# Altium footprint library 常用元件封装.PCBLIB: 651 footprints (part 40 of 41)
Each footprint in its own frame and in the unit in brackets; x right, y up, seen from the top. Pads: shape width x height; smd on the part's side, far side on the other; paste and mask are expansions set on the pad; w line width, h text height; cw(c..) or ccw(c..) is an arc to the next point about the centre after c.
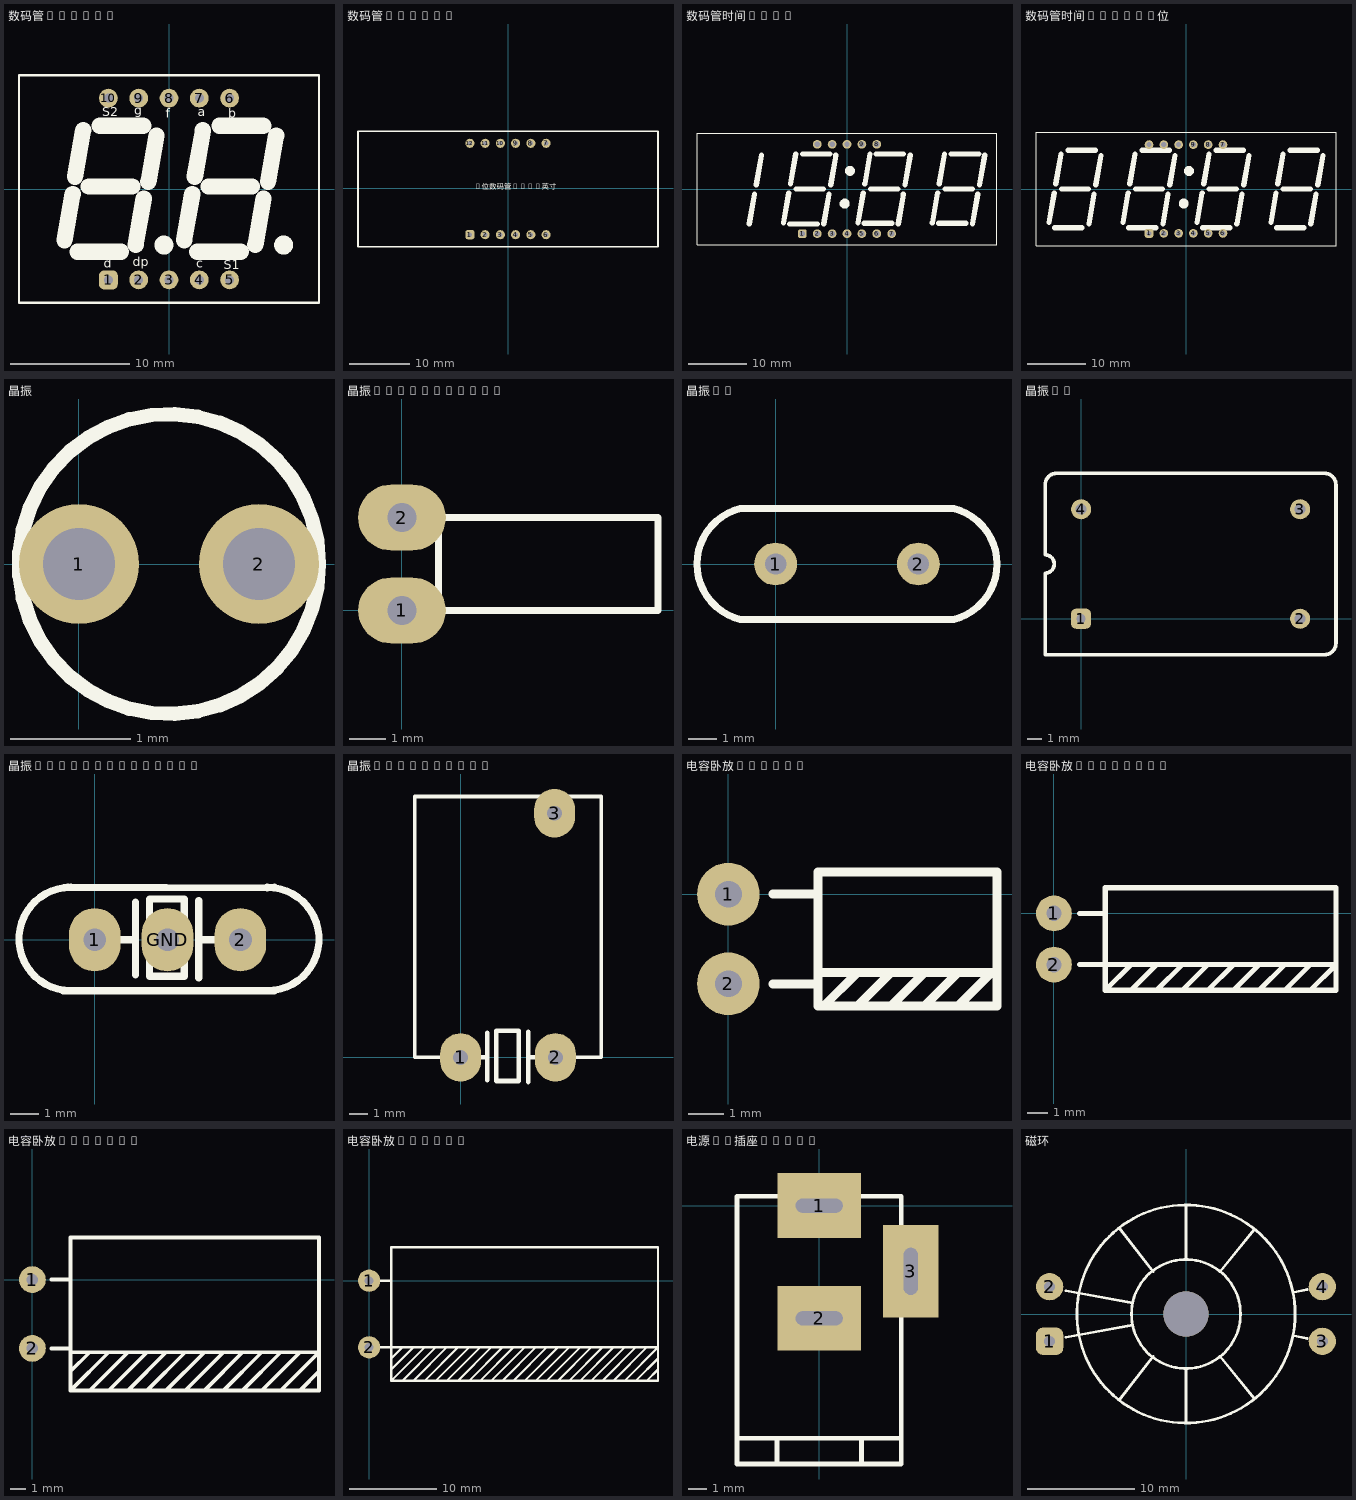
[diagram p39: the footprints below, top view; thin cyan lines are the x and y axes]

## 数码管0.56/2 [mil]
pads (10):
  rrect50% 62x62 hole 30: 1(-200,-300)
  round 62 hole 30: 2(-100,-300) 3(0,-300) 4(100,-300) 5(200,-300) 6(200,300) 7(100,300) 8(0,300) 9(-100,300) 10(-200,300)
TopOverlay:
  circle w39.37: c-16.65,-185 r11.65
  circle w39.37: c378.35,-185 r11.65
  lines w8: -495,-375 -495,375 495,375 495,-375 -495,-375
  lines w53.94: -345.05,-169.44 -318.18,-16.55 ; -310,40.42 -283.18,193.45 ; -301.9,-206.67 -158.18,-206.55 ; -264.89,8.45 -121.23,8.45 ; -228.18,208.45 -84.52,208.45 ; -110.17,-184.51 -83.18,-31.55 ; -68.18,23.45 -41.27,176.54 ; 49.95,-169.44 76.82,-16.55 ; 85,40.42 111.82,193.45 ; 93.1,-206.67 236.82,-206.55 ; 130.11,8.45 273.77,8.45 ; 166.82,208.45 310.48,208.45 ; 284.83,-184.51 311.82,-31.55 ; 326.82,23.45 353.73,176.54
  text "S1" at 180,-265 h30
  text "S2" at -220,240 h30
  text "g" at -115,245 h30
  text "f" at -10,235 h30
  text "a" at 95,240 h30
  text "b" at 195,235 h30
  text "d" at -215,-260 h30
  text "e" at -20,-200 h30
  text "c" at 90,-260 h30
  text "dp" at -120,-255 h30
  text "e" at 375,-200 h30

## 数码管0.56/4 [mil] "50.3mmX19mm"
pads (12):
  rrect50% 60x60 hole 30: 1(-250,-305)
  round 60 hole 30: 2(-150,-305) 3(-50,-305) 4(50,-305) 5(150,-305) 6(250,-305) 7(250,295) 8(150,295) 9(50,295) 10(-50,295) 11(-150,295) 12(-250,295)
TopOverlay:
  lines w10: -985,-385 970,-385 985,-385 985,375 -985,375 -985,-385
  text "4位数码管0.56英寸" at -220,-20 h60

## 数码管时间0.56 [mm] "LED, 7-Segment Display, 14.22 mm, Four Digit, 18:88; 12 Leads; Row Space 15.24 mm; Pitch 2.54 mm"
height 8.26
pads (12):
  rrect50% 1.5x1.5 hole 0.9: 1(-7.62,-7.62)
  round 1.5 hole 0.9: 2(-5.08,-7.62) 3(-2.54,-7.62) 4(0,-7.62) 5(2.54,-7.62) 6(5.08,-7.62) 7(7.62,-7.62) 8(5.08,7.62) 9(2.54,7.62) 10(0,7.62) 11(-2.54,7.62) 12(-5.08,7.62)
TopOverlay:
  circle w1.4: c0.505,3.1 r0.15
  circle w1.4: c-0.395,-2.5 r0.15
  lines w0.2: -25.6,-9.55 25.6,-9.55 25.6,9.55 -25.6,9.55 -25.6,-9.55
  lines w0.9: -16.67,-5.95 -15.78,-0.9 ; -15.49,0.71 -14.6,5.76 ; -10.83,-5.76 -9.93,-0.69 ; -9.75,-5.959 -5.08,-5.969 ; -9.65,0.9 -8.76,5.96 ; -8.69,0 -4.03,0 ; -7.591,5.969 -2.921,5.969 ; -3.97,-5.95 -3.08,-0.9 ; -2.79,0.71 -1.9,5.76 ; 1.87,-5.76 2.77,-0.69 ; 2.95,-5.832 7.62,-5.842 ; 3.05,0.9 3.94,5.96 ; 4.01,0 8.67,0 ; 4.982,5.969 9.652,5.969 ; 8.73,-5.95 9.62,-0.9 ; 9.91,0.71 10.8,5.76 ; 14.57,-5.76 15.47,-0.69 ; 15.65,-5.832 20.32,-5.842 ; 15.75,0.9 16.64,5.96 ; 16.71,0 21.37,0 ; 17.809,5.969 22.479,5.969 ; 21.43,-5.95 22.32,-0.9 ; 22.61,0.71 23.5,5.76

## 数码管时间0.56/4位 [mm] "LED, 7-Segment Display, 14.22 mm, Four Digit, 88:88; 12 Leads; Row Space 15.24 mm; Pitch 2.54 mm"
height 8.26
pads (12):
  rrect50% 1.5x1.5 hole 0.9: 1(-6.35,-7.62)
  round 1.5 hole 0.9: 2(-3.81,-7.62) 3(-1.27,-7.62) 4(1.27,-7.62) 5(3.81,-7.62) 6(6.35,-7.62) 7(6.35,7.62) 8(3.81,7.62) 9(1.27,7.62) 10(-1.27,7.62) 11(-3.81,7.62) 12(-6.35,7.62)
TopOverlay:
  circle w1.4: c-0.395,-2.5 r0.15
  circle w1.4: c0.505,3.1 r0.15
  lines w0.2: -25.75,-9.7 25.75,-9.7 25.75,9.7 -25.75,9.7 -25.75,-9.7
  lines w0.9: -23.53,-5.76 -22.63,-0.69 ; -22.57,-6.66 -17.9,-6.67 ; -22.35,0.9 -21.46,5.96 ; -21.39,0 -16.73,0 ; -20.23,6.66 -15.56,6.66 ; -16.67,-5.95 -15.78,-0.9 ; -15.49,0.71 -14.6,5.76 ; -10.83,-5.76 -9.93,-0.69 ; -9.87,-6.66 -5.2,-6.67 ; -9.65,0.9 -8.76,5.96 ; -8.69,0 -4.03,0 ; -7.53,6.66 -2.86,6.66 ; -3.97,-5.95 -3.08,-0.9 ; -2.79,0.71 -1.9,5.76 ; 1.87,-5.76 2.77,-0.69 ; 2.83,-6.66 7.5,-6.67 ; 3.05,0.9 3.94,5.96 ; 4.01,0 8.67,0 ; 5.17,6.66 9.84,6.66 ; 8.73,-5.95 9.62,-0.9 ; 9.91,0.71 10.8,5.76 ; 14.57,-5.76 15.47,-0.69 ; 15.53,-6.66 20.2,-6.67 ; 15.75,0.9 16.64,5.96 ; 16.71,0 21.37,0 ; 17.87,6.66 22.54,6.66 ; 21.43,-5.95 22.32,-0.9 ; 22.61,0.71 23.5,5.76

## 晶振 [mm] "1.5mm"
pads (2):
  round 1 hole 0.6: 1(0,0) 2(1.5,0)
TopOverlay:
  circle w0.12: c0.75,0 r1.25

## 晶振2.5/2/6/2.5 [mm]
pads (2):
  oval 2.4x1.8 hole 0.8: 1(0,0) 2(0,2.54)
TopOverlay:
  lines w0.2: 0,0 7,0 7,2.54 0,2.54 ; 1,0 1,2.54
BottomOverlay:
  lines w0.2: 1.524,0 2.54,0 2.54,0.508 ; 1.524,0.508 2.54,0.508 ; 1.524,2.032 2.54,2.032 ; 1.524,2.54 2.54,2.54 2.54,2.032 ; 3.556,0.508 2.54,0.508 ; 3.556,2.032 2.54,2.032 ; 1.524,1.016 3.556,1.016 3.556,1.524 1.524,1.524 1.524,1.016

## 晶振-1 [mil] "5.08MM"
pads (2):
  round 60 hole 30: 1(0,0) 2(200,0)
TopOverlay:
  lines w10: -49.4,-77.61 cw(c-30,0) -49.4,77.61 249.4,77.61 cw(c230,0) 249.4,-77.61 -49.4,-77.61

## 晶振-3 [mil] "15.24mmX7.62mm"
pads (4):
  rrect50% 55x55 hole 25: 1(0,0)
  round 55 hole 30: 2(600,0) 3(600,300) 4(0,300)
TopOverlay:
  lines w10: -98.5,-98.5 667,-98.5 ccw(c667,-67) 698.5,-67 698.5,367 ccw(c667,367) 667,398.5 -66.5,398.5 ; -98.5,-98.44 -98.5,124 ; -98.5,125 ccw(c-98.5,150) -98.5,175 -98.5,367 cw(c-67,367) -67,398.5

## 晶振/2.5/3/10/5/E2 [mm]
pads (3):
  oval 1.8x2.2 hole 0.8: 1(0,0) 2(5.08,0) GND(2.54,0)
TopOverlay:
  lines w0.254: -1.1,-1.775 6.266,-1.775 ; -0.94,1.829 6.02,1.803 6.274,1.829 ; -0.838,-1.778 cw(c-0.838,0.025) -0.838,1.829 ; 0,0 1.35,0 ; 1.424,-1.225 1.424,1.315 ; 3.624,-1.325 3.624,1.367 ; 3.65,0 5.08,0 ; 6.02,-1.778 ccw(c6.02,0.025) 6.02,1.829 ; 1.911,-1.27 3.119,-1.27 3.119,1.422 1.911,1.422 1.911,-1.27
BottomOverlay:
  lines w0.254: 0.92,0 1.07,0 ; 1.144,-1.225 1.144,1.315 ; 3.944,-1.325 3.944,1.367 ; 3.99,0 4.12,0 ; 1.631,-1.27 1.631,1.422 3.439,1.422 3.439,-1.27 1.631,-1.27

## 晶振/5/3/14/10 [mm]
pads (3):
  oval 2.2x2.6 hole 0.8: 1(0,0) 2(5.08,0) 3(5.04,13.1)
TopOverlay:
  lines w0.2: 0,0 -2.46,0 -2.46,14 7.54,14 7.54,0 5.08,0
  lines w0.254: 0,0 1.35,0 ; 1.424,-1.225 1.424,1.315 ; 3.624,-1.325 3.624,1.367 ; 3.65,0 5.08,0 ; 1.911,-1.27 1.911,1.422 3.119,1.422 3.119,-1.27 1.911,-1.27
BottomOverlay:
  lines w0.2: -1.66,-1.7 -1.66,1.7 6.74,1.7 6.74,-1.7 -1.66,-1.7
  lines w0.254: 1.45,0 1.6,0 ; 1.744,-1.225 1.744,1.315 ; 3.344,-1.325 3.344,1.367 ; 3.5,0 3.63,0 ; 2.231,-1.27 2.839,-1.27 2.839,1.422 2.231,1.422 2.231,-1.27

## 电容卧放2.54mm [mil] "5.5mmX4mm"
pads (2):
  round 70 hole 30: 1(0,0) 2(0,-100)
TopOverlay:
  lines w10: 50,-100 100,-100 ; 50,0 100,0 ; 100,-87.5 300,-87.5 ; 106.25,-125 143.75,-87.5 ; 143.75,-125 181.25,-87.5 ; 181.25,-125 218.75,-87.5 ; 218.75,-125 256.25,-87.5 ; 256.25,-125 293.75,-87.5 ; 100,-125 100,25 300,25 300,-125 100,-125

## 电容卧放2.54mm-1 [mil] "11.6mmX5.3mm"
pads (2):
  round 70 hole 30: 1(0,0) 2(0,-100)
TopOverlay:
  lines w10: 50,-100 550,-100 500,-150 ; 50,0 100,0 ; 150,-150 200,-100 ; 150,-100 100,-150 ; 200,-150 250,-100 ; 250,-150 300,-100 ; 300,-150 350,-100 ; 350,-150 400,-100 ; 400,-150 450,-100 ; 450,-150 500,-100 ; 100,-150 550,-150 550,50 100,50 100,-150

## 电容卧放4.572mm [mil] "16.8mmX10.5mm"
pads (2):
  round 70 hole 30: 1(0,0) 2(0,-180)
TopOverlay:
  lines w10: 50,-180 100,-180 ; 50,0 100,0 ; 100,-240 150,-190 ; 100,-190 750,-190 650,-290 ; 150,-290 250,-190 ; 200,-290 300,-190 ; 200,-190 100,-290 ; 250,-290 350,-190 ; 300,-290 400,-190 ; 350,-290 450,-190 ; 400,-290 500,-190 ; 450,-290 550,-190 ; 500,-290 600,-190 ; 550,-290 650,-190 ; 600,-290 700,-190 ; 700,-290 750,-240 ; 100,-290 100,110 750,110 750,-290 100,-290

## 电容卧放7.62mm [mm] "30.5mmX15.5mm"
pads (2):
  round 2.54 hole 1: 1(0,0) 2(0,-7.62)
TopOverlay:
  lines w0.254: 1.27,-7.62 33.02,-7.62 29.21,-11.43 ; 1.27,0 2.54,0 ; 2.54,-10.16 5.08,-7.62 ; 2.54,-8.89 3.81,-7.62 ; 3.81,-11.43 7.62,-7.62 ; 5.08,-11.43 8.89,-7.62 ; 6.35,-11.43 10.16,-7.62 ; 6.35,-7.62 2.54,-11.43 ; 7.62,-11.43 11.43,-7.62 ; 8.89,-11.43 12.7,-7.62 ; 10.16,-11.43 13.97,-7.62 ; 11.43,-11.43 15.24,-7.62 ; 12.7,-11.43 16.51,-7.62 ; 13.97,-11.43 17.78,-7.62 ; 15.24,-11.43 19.05,-7.62 ; 16.51,-11.43 20.32,-7.62 ; 17.78,-11.43 21.59,-7.62 ; 19.05,-11.43 22.86,-7.62 ; 20.32,-11.43 24.13,-7.62 ; 21.59,-11.43 25.4,-7.62 ; 22.86,-11.43 26.67,-7.62 ; 24.13,-11.43 27.94,-7.62 ; 25.4,-11.43 29.21,-7.62 ; 26.67,-11.43 30.48,-7.62 ; 27.94,-11.43 31.75,-7.62 ; 30.48,-11.43 33.02,-8.89 ; 31.75,-11.43 33.02,-10.16 ; 2.54,-11.43 33.02,-11.43 33.02,3.81 2.54,3.81 2.54,-11.43

## 电源DC插座5.4mm [mil]
height 433.07
pads (3):
  rect 177.17x137.8 hole 30 slot 100 at 0 deg: 1(0,0) 2(0,-240)
  rect 118.11x196.85 hole 30 slot 100 at 90 deg: 3(195,-140)
TopOverlay:
  lines w10: -175,-495 175,-495 ; -90,-550 -90,-495 ; 90,-550 90,-495 ; -175,-550 -175,20 175,20 175,-550 -175,-550

## 磁环 [mil] "外径20.32mm脚距25.4mm"
pads (4):
  rrect50% 100x100 hole 40: 1(-500,-100)
  round 100 hole 40: 2(-500,100) 3(500,-100) 4(500,100)
via 0,0 diameter 165.35 hole 165.35
TopOverlay:
  circle w10: c0,0 r400
  circle w10: c0,0 r200
  lines w10: -440,-85 -195,-40 ; -440,85 -195,40 ; -245,-315 -120,-155 ; -245,315 -120,155 ; 0,-400 0,-200 ; 0,200 0,400 ; 125,-155 250,-310 ; 125,155 250,310 ; 395,-80 445,-90 ; 395,80 445,90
